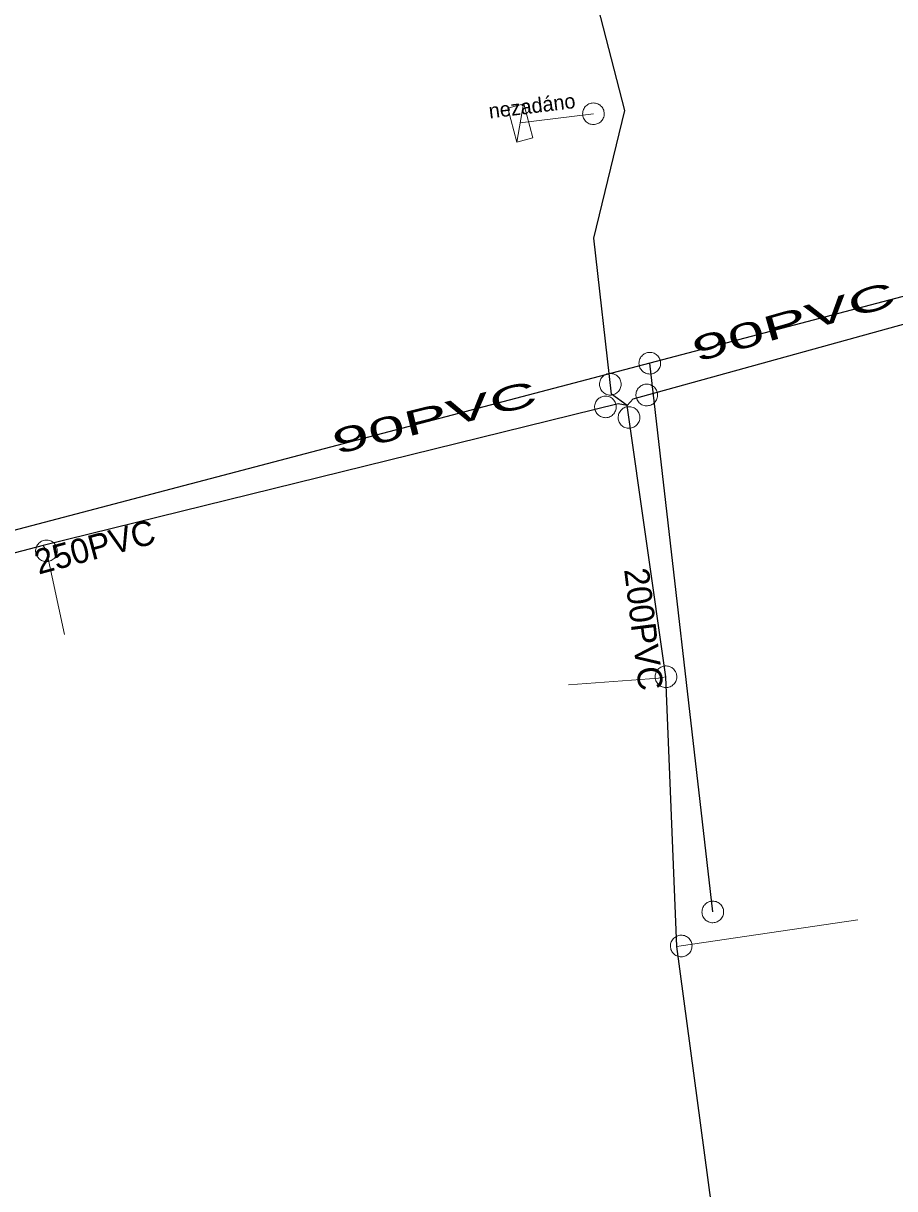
# Model space of a CAD drawing. Extents: x -741806 to -738704, y -1059275 to -1055387.
# Drawn here: x -740624.24 to -740588.96, y -1057303.21 to -1057256.02 of the extents above; entities that cross this region are included whole.
import ezdxf

# ---------------------------------------------------------------- set-up
doc = ezdxf.new("R2010")
doc.units = 0
doc.header["$LTSCALE"] = 0.4
for name, color, linetype, lineweight in [('2', 7, 'Continuous', 25), ('21', 7, 'Continuous', 13), ('3', 7, 'Continuous', 13), ('46', 7, 'Continuous', 13), ('51', 7, 'Continuous', 13), ('52', 7, 'Continuous', 25), ('56', 7, 'Continuous', 13)]:
    doc.layers.add(name, color=color, linetype=linetype, lineweight=lineweight)
for name, color, linetype in [('5', 7, 'Continuous'), ('53', 7, 'Continuous'), ('55', 7, 'Continuous')]:
    doc.layers.add(name, color=color, linetype=linetype)

msp = doc.modelspace()

# ---------------------------------------------------------------- linework, layer by layer
at = {"layer": '2'}
for p in [(-740573.78, -1057263.169), (-740596.329, -1057292)]:
    msp.add_line(p, (-740598.879, -1057269.78), dxfattribs=at)
msp.add_lwpolyline([(-740598.879, -1057269.78), (-740643.57, -1057281.54), (-740672.23, -1057290.27), (-740701.8, -1057300.899)], dxfattribs=at)
at = {"layer": '21'}
for points in [[(-740623.436, -1057277.166), (-740623.3, -1057277.379), (-740622.572, -1057280.771)], [(-740598.223, -1057282.477), (-740598.526, -1057282.531), (-740602.17, -1057282.806)], [(-740597.782, -1057293.399), (-740597.605, -1057293.378), (-740590.458, -1057292.324)]]:
    msp.add_lwpolyline(points, dxfattribs=at)
at = {"layer": '3'}
for points in [[(-740601.254, -1057259.251), (-740601.297, -1057259.264), (-740601.34, -1057259.28), (-740601.381, -1057259.302), (-740601.419, -1057259.326), (-740601.454, -1057259.356), (-740601.487, -1057259.389), (-740601.515, -1057259.424), (-740601.54, -1057259.463), (-740601.559, -1057259.504), (-740601.576, -1057259.547), (-740601.587, -1057259.591), (-740601.594, -1057259.637), (-740601.596, -1057259.682), (-740601.594, -1057259.728), (-740601.586, -1057259.773), (-740601.574, -1057259.818), (-740601.556, -1057259.86), (-740601.536, -1057259.9), (-740601.51, -1057259.939), (-740601.481, -1057259.974), (-740601.448, -1057260.006), (-740601.413, -1057260.034), (-740601.374, -1057260.059), (-740601.333, -1057260.08), (-740601.29, -1057260.096), (-740601.245, -1057260.106), (-740601.201, -1057260.114), (-740601.154, -1057260.116), (-740601.109, -1057260.113), (-740601.063, -1057260.105), (-740601.02, -1057260.093), (-740600.977, -1057260.076), (-740600.936, -1057260.055), (-740600.898, -1057260.029), (-740600.863, -1057260.001), (-740600.83, -1057259.968), (-740600.803, -1057259.932), (-740600.777, -1057259.893), (-740600.758, -1057259.853), (-740600.742, -1057259.81), (-740600.73, -1057259.765), (-740600.723, -1057259.72), (-740600.72, -1057259.674), (-740600.723, -1057259.629), (-740600.731, -1057259.583), (-740600.743, -1057259.539), (-740600.76, -1057259.497), (-740600.781, -1057259.456), (-740600.807, -1057259.418), (-740600.837, -1057259.382), (-740600.869, -1057259.351), (-740600.904, -1057259.322), (-740600.943, -1057259.298), (-740600.984, -1057259.277), (-740601.027, -1057259.261), (-740601.072, -1057259.249), (-740601.116, -1057259.243), (-740601.163, -1057259.241), (-740601.208, -1057259.244), (-740601.253, -1057259.251)], [(-740598.928, -1057269.344), (-740598.972, -1057269.352), (-740599.016, -1057269.364), (-740599.06, -1057269.382), (-740599.099, -1057269.402), (-740599.138, -1057269.428), (-740599.174, -1057269.457), (-740599.205, -1057269.49), (-740599.234, -1057269.525), (-740599.258, -1057269.564), (-740599.279, -1057269.605), (-740599.295, -1057269.648), (-740599.307, -1057269.693), (-740599.313, -1057269.738), (-740599.315, -1057269.783), (-740599.312, -1057269.829), (-740599.305, -1057269.875), (-740599.292, -1057269.919), (-740599.276, -1057269.961), (-740599.254, -1057270.002), (-740599.229, -1057270.04), (-740599.199, -1057270.075), (-740599.168, -1057270.107), (-740599.131, -1057270.136), (-740599.093, -1057270.16), (-740599.051, -1057270.181), (-740599.008, -1057270.196), (-740598.965, -1057270.208), (-740598.919, -1057270.215), (-740598.873, -1057270.217), (-740598.827, -1057270.213), (-740598.783, -1057270.206), (-740598.739, -1057270.194), (-740598.695, -1057270.177), (-740598.655, -1057270.155), (-740598.617, -1057270.131), (-740598.581, -1057270.102), (-740598.55, -1057270.069), (-740598.521, -1057270.032), (-740598.497, -1057269.994), (-740598.477, -1057269.954), (-740598.46, -1057269.911), (-740598.448, -1057269.866), (-740598.441, -1057269.821), (-740598.44, -1057269.775), (-740598.443, -1057269.73), (-740598.45, -1057269.684), (-740598.462, -1057269.64), (-740598.479, -1057269.598), (-740598.501, -1057269.557), (-740598.526, -1057269.519), (-740598.556, -1057269.484), (-740598.588, -1057269.451), (-740598.624, -1057269.423), (-740598.662, -1057269.398), (-740598.704, -1057269.378), (-740598.747, -1057269.362), (-740598.79, -1057269.351), (-740598.836, -1057269.344), (-740598.882, -1057269.342), (-740598.927, -1057269.344)], [(-740596.378, -1057291.564), (-740596.422, -1057291.572), (-740596.466, -1057291.584), (-740596.51, -1057291.602), (-740596.549, -1057291.622), (-740596.588, -1057291.648), (-740596.624, -1057291.677), (-740596.655, -1057291.71), (-740596.684, -1057291.745), (-740596.708, -1057291.784), (-740596.729, -1057291.825), (-740596.745, -1057291.868), (-740596.757, -1057291.913), (-740596.763, -1057291.958), (-740596.765, -1057292.003), (-740596.762, -1057292.049), (-740596.755, -1057292.095), (-740596.742, -1057292.139), (-740596.726, -1057292.181), (-740596.704, -1057292.222), (-740596.679, -1057292.26), (-740596.649, -1057292.295), (-740596.618, -1057292.327), (-740596.581, -1057292.356), (-740596.543, -1057292.38), (-740596.501, -1057292.401), (-740596.458, -1057292.416), (-740596.415, -1057292.428), (-740596.369, -1057292.435), (-740596.323, -1057292.437), (-740596.277, -1057292.433), (-740596.233, -1057292.426), (-740596.189, -1057292.414), (-740596.145, -1057292.397), (-740596.105, -1057292.375), (-740596.067, -1057292.351), (-740596.031, -1057292.322), (-740596, -1057292.289), (-740595.971, -1057292.252), (-740595.947, -1057292.214), (-740595.927, -1057292.174), (-740595.91, -1057292.131), (-740595.898, -1057292.086), (-740595.891, -1057292.041), (-740595.89, -1057291.995), (-740595.893, -1057291.95), (-740595.9, -1057291.904), (-740595.912, -1057291.86), (-740595.929, -1057291.818), (-740595.951, -1057291.777), (-740595.976, -1057291.739), (-740596.006, -1057291.704), (-740596.038, -1057291.671), (-740596.074, -1057291.643), (-740596.112, -1057291.618), (-740596.154, -1057291.598), (-740596.197, -1057291.582), (-740596.24, -1057291.571), (-740596.286, -1057291.564), (-740596.332, -1057291.562), (-740596.377, -1057291.564)]]:
    msp.add_lwpolyline(points, dxfattribs=at)
at = {"layer": '46'}
msp.add_line((-740603.983, -1057259.277), (-740604.257, -1057260.822), dxfattribs=at)
msp.add_lwpolyline([(-740603.981, -1057259.277), (-740603.614, -1057260.649), (-740604.259, -1057260.822), (-740604.626, -1057259.45)], close=True, dxfattribs=at)
at = {"layer": '51'}
for points in [[(-740600.038, -1057270.632), (-740600.039, -1057270.587), (-740600.047, -1057270.542), (-740600.059, -1057270.497), (-740600.075, -1057270.455), (-740600.096, -1057270.414), (-740600.12, -1057270.375), (-740600.15, -1057270.34), (-740600.182, -1057270.307), (-740600.218, -1057270.279), (-740600.255, -1057270.254), (-740600.297, -1057270.233), (-740600.34, -1057270.216), (-740600.384, -1057270.204), (-740600.429, -1057270.197), (-740600.475, -1057270.195), (-740600.521, -1057270.197), (-740600.566, -1057270.204), (-740600.61, -1057270.216), (-740600.652, -1057270.233), (-740600.694, -1057270.254), (-740600.732, -1057270.279), (-740600.767, -1057270.307), (-740600.799, -1057270.34), (-740600.829, -1057270.375), (-740600.853, -1057270.414), (-740600.875, -1057270.455), (-740600.891, -1057270.497), (-740600.902, -1057270.542), (-740600.91, -1057270.587), (-740600.913, -1057270.633), (-740600.91, -1057270.678), (-740600.902, -1057270.723), (-740600.891, -1057270.768), (-740600.875, -1057270.81), (-740600.853, -1057270.851), (-740600.829, -1057270.89), (-740600.799, -1057270.925), (-740600.767, -1057270.958), (-740600.732, -1057270.986), (-740600.694, -1057271.011), (-740600.652, -1057271.032), (-740600.61, -1057271.049), (-740600.566, -1057271.06), (-740600.521, -1057271.068), (-740600.475, -1057271.07), (-740600.429, -1057271.068), (-740600.384, -1057271.06), (-740600.34, -1057271.049), (-740600.297, -1057271.032), (-740600.255, -1057271.011), (-740600.218, -1057270.986), (-740600.182, -1057270.958), (-740600.15, -1057270.925), (-740600.12, -1057270.89), (-740600.096, -1057270.851), (-740600.075, -1057270.81), (-740600.059, -1057270.768), (-740600.047, -1057270.723), (-740600.039, -1057270.678), (-740600.038, -1057270.633)], [(-740598.579, -1057270.951), (-740598.593, -1057270.908), (-740598.612, -1057270.866), (-740598.635, -1057270.826), (-740598.662, -1057270.79), (-740598.693, -1057270.756), (-740598.728, -1057270.725), (-740598.765, -1057270.699), (-740598.805, -1057270.676), (-740598.847, -1057270.658), (-740598.89, -1057270.644), (-740598.935, -1057270.635), (-740598.981, -1057270.63), (-740599.027, -1057270.63), (-740599.072, -1057270.635), (-740599.117, -1057270.646), (-740599.161, -1057270.66), (-740599.202, -1057270.679), (-740599.241, -1057270.702), (-740599.278, -1057270.73), (-740599.312, -1057270.761), (-740599.342, -1057270.795), (-740599.369, -1057270.832), (-740599.391, -1057270.872), (-740599.41, -1057270.914), (-740599.424, -1057270.958), (-740599.433, -1057271.003), (-740599.437, -1057271.048), (-740599.437, -1057271.094), (-740599.432, -1057271.14), (-740599.422, -1057271.185), (-740599.407, -1057271.227), (-740599.389, -1057271.269), (-740599.365, -1057271.309), (-740599.338, -1057271.345), (-740599.307, -1057271.379), (-740599.273, -1057271.41), (-740599.236, -1057271.436), (-740599.196, -1057271.459), (-740599.154, -1057271.477), (-740599.11, -1057271.491), (-740599.065, -1057271.5), (-740599.019, -1057271.505), (-740598.974, -1057271.504), (-740598.929, -1057271.499), (-740598.884, -1057271.489), (-740598.84, -1057271.475), (-740598.799, -1057271.455), (-740598.759, -1057271.433), (-740598.722, -1057271.405), (-740598.688, -1057271.374), (-740598.658, -1057271.34), (-740598.631, -1057271.303), (-740598.609, -1057271.263), (-740598.59, -1057271.221), (-740598.577, -1057271.177), (-740598.567, -1057271.132), (-740598.563, -1057271.087), (-740598.564, -1057271.041), (-740598.569, -1057270.995), (-740598.579, -1057270.952)], [(-740601.097, -1057271.653), (-740601.084, -1057271.696), (-740601.067, -1057271.738), (-740601.044, -1057271.779), (-740601.019, -1057271.816), (-740600.988, -1057271.85), (-740600.955, -1057271.882), (-740600.918, -1057271.909), (-740600.879, -1057271.934), (-740600.838, -1057271.952), (-740600.795, -1057271.967), (-740600.75, -1057271.978), (-740600.704, -1057271.984), (-740600.658, -1057271.985), (-740600.613, -1057271.981), (-740600.568, -1057271.972), (-740600.524, -1057271.959), (-740600.482, -1057271.942), (-740600.442, -1057271.92), (-740600.404, -1057271.893), (-740600.369, -1057271.863), (-740600.339, -1057271.829), (-740600.31, -1057271.793), (-740600.287, -1057271.754), (-740600.267, -1057271.713), (-740600.252, -1057271.669), (-740600.242, -1057271.624), (-740600.236, -1057271.579), (-740600.236, -1057271.533), (-740600.24, -1057271.487), (-740600.248, -1057271.442), (-740600.261, -1057271.399), (-740600.279, -1057271.357), (-740600.301, -1057271.316), (-740600.327, -1057271.279), (-740600.357, -1057271.245), (-740600.391, -1057271.213), (-740600.427, -1057271.186), (-740600.466, -1057271.161), (-740600.508, -1057271.143), (-740600.551, -1057271.128), (-740600.596, -1057271.117), (-740600.641, -1057271.111), (-740600.687, -1057271.111), (-740600.732, -1057271.114), (-740600.778, -1057271.123), (-740600.822, -1057271.136), (-740600.864, -1057271.154), (-740600.904, -1057271.176), (-740600.941, -1057271.202), (-740600.976, -1057271.233), (-740601.007, -1057271.266), (-740601.035, -1057271.302), (-740601.058, -1057271.341), (-740601.078, -1057271.382), (-740601.093, -1057271.426), (-740601.104, -1057271.471), (-740601.109, -1057271.516), (-740601.11, -1057271.562), (-740601.106, -1057271.608), (-740601.097, -1057271.652)], [(-740599.781, -1057271.545), (-740599.825, -1057271.553), (-740599.868, -1057271.566), (-740599.911, -1057271.585), (-740599.951, -1057271.606), (-740599.988, -1057271.633), (-740600.023, -1057271.663), (-740600.054, -1057271.697), (-740600.082, -1057271.733), (-740600.105, -1057271.773), (-740600.124, -1057271.814), (-740600.139, -1057271.858), (-740600.15, -1057271.902), (-740600.156, -1057271.948), (-740600.156, -1057271.993), (-740600.152, -1057272.039), (-740600.143, -1057272.084), (-740600.13, -1057272.128), (-740600.112, -1057272.17), (-740600.089, -1057272.21), (-740600.062, -1057272.248), (-740600.032, -1057272.282), (-740599.999, -1057272.313), (-740599.962, -1057272.34), (-740599.923, -1057272.364), (-740599.881, -1057272.383), (-740599.838, -1057272.398), (-740599.794, -1057272.408), (-740599.748, -1057272.414), (-740599.702, -1057272.414), (-740599.656, -1057272.411), (-740599.612, -1057272.402), (-740599.569, -1057272.388), (-740599.526, -1057272.37), (-740599.486, -1057272.348), (-740599.449, -1057272.322), (-740599.414, -1057272.291), (-740599.383, -1057272.258), (-740599.355, -1057272.222), (-740599.332, -1057272.182), (-740599.313, -1057272.141), (-740599.298, -1057272.097), (-740599.287, -1057272.052), (-740599.282, -1057272.007), (-740599.281, -1057271.961), (-740599.285, -1057271.916), (-740599.294, -1057271.87), (-740599.308, -1057271.827), (-740599.325, -1057271.785), (-740599.348, -1057271.745), (-740599.375, -1057271.707), (-740599.405, -1057271.673), (-740599.438, -1057271.641), (-740599.475, -1057271.614), (-740599.514, -1057271.591), (-740599.556, -1057271.571), (-740599.599, -1057271.556), (-740599.643, -1057271.546), (-740599.689, -1057271.541), (-740599.735, -1057271.54), (-740599.78, -1057271.545)], [(-740623.064, -1057277.746), (-740623.027, -1057277.72), (-740622.993, -1057277.69), (-740622.961, -1057277.656), (-740622.935, -1057277.619), (-740622.912, -1057277.58), (-740622.892, -1057277.537), (-740622.879, -1057277.494), (-740622.868, -1057277.449), (-740622.864, -1057277.404), (-740622.864, -1057277.358), (-740622.868, -1057277.313), (-740622.877, -1057277.267), (-740622.891, -1057277.224), (-740622.909, -1057277.182), (-740622.932, -1057277.142), (-740622.959, -1057277.105), (-740622.989, -1057277.071), (-740623.023, -1057277.04), (-740623.061, -1057277.013), (-740623.1, -1057276.99), (-740623.142, -1057276.972), (-740623.185, -1057276.957), (-740623.23, -1057276.947), (-740623.275, -1057276.942), (-740623.322, -1057276.942), (-740623.367, -1057276.947), (-740623.411, -1057276.956), (-740623.456, -1057276.97), (-740623.497, -1057276.989), (-740623.538, -1057277.011), (-740623.574, -1057277.038), (-740623.608, -1057277.068), (-740623.639, -1057277.102), (-740623.666, -1057277.139), (-740623.689, -1057277.178), (-740623.708, -1057277.221), (-740623.722, -1057277.264), (-740623.733, -1057277.309), (-740623.737, -1057277.354), (-740623.737, -1057277.4), (-740623.733, -1057277.445), (-740623.724, -1057277.491), (-740623.709, -1057277.534), (-740623.692, -1057277.576), (-740623.668, -1057277.616), (-740623.642, -1057277.653), (-740623.611, -1057277.687), (-740623.578, -1057277.718), (-740623.54, -1057277.745), (-740623.5, -1057277.768), (-740623.459, -1057277.786), (-740623.416, -1057277.802), (-740623.371, -1057277.811), (-740623.325, -1057277.816), (-740623.279, -1057277.816), (-740623.233, -1057277.811), (-740623.189, -1057277.802), (-740623.145, -1057277.788), (-740623.103, -1057277.77), (-740623.064, -1057277.747)], [(-740598.653, -1057282.553), (-740598.643, -1057282.597), (-740598.628, -1057282.64), (-740598.608, -1057282.682), (-740598.585, -1057282.72), (-740598.557, -1057282.757), (-740598.526, -1057282.791), (-740598.491, -1057282.821), (-740598.454, -1057282.847), (-740598.414, -1057282.869), (-740598.372, -1057282.887), (-740598.328, -1057282.9), (-740598.283, -1057282.909), (-740598.237, -1057282.913), (-740598.192, -1057282.912), (-740598.146, -1057282.906), (-740598.101, -1057282.896), (-740598.058, -1057282.881), (-740598.017, -1057282.862), (-740597.977, -1057282.838), (-740597.941, -1057282.81), (-740597.908, -1057282.778), (-740597.877, -1057282.745), (-740597.851, -1057282.706), (-740597.829, -1057282.667), (-740597.811, -1057282.624), (-740597.798, -1057282.58), (-740597.789, -1057282.536), (-740597.785, -1057282.49), (-740597.786, -1057282.444), (-740597.792, -1057282.398), (-740597.802, -1057282.354), (-740597.817, -1057282.311), (-740597.837, -1057282.269), (-740597.86, -1057282.231), (-740597.888, -1057282.194), (-740597.919, -1057282.16), (-740597.954, -1057282.131), (-740597.991, -1057282.104), (-740598.032, -1057282.082), (-740598.073, -1057282.064), (-740598.118, -1057282.051), (-740598.163, -1057282.042), (-740598.208, -1057282.039), (-740598.254, -1057282.039), (-740598.299, -1057282.045), (-740598.344, -1057282.055), (-740598.387, -1057282.071), (-740598.429, -1057282.089), (-740598.468, -1057282.113), (-740598.505, -1057282.141), (-740598.538, -1057282.173), (-740598.568, -1057282.206), (-740598.594, -1057282.245), (-740598.616, -1057282.284), (-740598.634, -1057282.327), (-740598.648, -1057282.371), (-740598.656, -1057282.415), (-740598.66, -1057282.462), (-740598.659, -1057282.507), (-740598.653, -1057282.552)], [(-740597.171, -1057293.326), (-740597.178, -1057293.282), (-740597.19, -1057293.238), (-740597.207, -1057293.195), (-740597.228, -1057293.155), (-740597.254, -1057293.117), (-740597.283, -1057293.081), (-740597.316, -1057293.05), (-740597.352, -1057293.021), (-740597.391, -1057292.997), (-740597.432, -1057292.977), (-740597.475, -1057292.961), (-740597.52, -1057292.949), (-740597.565, -1057292.942), (-740597.61, -1057292.941), (-740597.656, -1057292.944), (-740597.702, -1057292.952), (-740597.746, -1057292.964), (-740597.788, -1057292.981), (-740597.828, -1057293.003), (-740597.867, -1057293.029), (-740597.901, -1057293.058), (-740597.934, -1057293.09), (-740597.962, -1057293.127), (-740597.986, -1057293.165), (-740598.007, -1057293.206), (-740598.023, -1057293.25), (-740598.034, -1057293.293), (-740598.04, -1057293.339), (-740598.042, -1057293.385), (-740598.039, -1057293.431), (-740598.031, -1057293.475), (-740598.019, -1057293.519), (-740598.001, -1057293.562), (-740597.981, -1057293.602), (-740597.955, -1057293.64), (-740597.925, -1057293.676), (-740597.892, -1057293.707), (-740597.857, -1057293.736), (-740597.818, -1057293.76), (-740597.777, -1057293.78), (-740597.734, -1057293.796), (-740597.689, -1057293.808), (-740597.644, -1057293.814), (-740597.598, -1057293.816), (-740597.553, -1057293.813), (-740597.507, -1057293.805), (-740597.463, -1057293.792), (-740597.421, -1057293.776), (-740597.38, -1057293.754), (-740597.342, -1057293.728), (-740597.307, -1057293.699), (-740597.275, -1057293.667), (-740597.247, -1057293.63), (-740597.222, -1057293.592), (-740597.202, -1057293.551), (-740597.186, -1057293.507), (-740597.175, -1057293.464), (-740597.169, -1057293.418), (-740597.167, -1057293.372), (-740597.17, -1057293.327)]]:
    msp.add_lwpolyline(points, dxfattribs=at)
at = {"layer": '52'}
for points in [[(-740599.789, -1057271.49), (-740600.43, -1057271.03), (-740601.149, -1057264.71), (-740599.89, -1057259.55), (-740605.469, -1057237.879), (-740606.21, -1057235.75), (-740610.079, -1057216.44), (-740610.699, -1057213.46), (-740613.21, -1057198.96), (-740635.57, -1057204.919), (-740654.67, -1057209.71), (-740658.96, -1057210.78), (-740671.342, -1057213.918), (-740678.14, -1057215.639), (-740680.199, -1057216.11)], [(-740599.789, -1057271.49), (-740599.544, -1057271.217), (-740577.079, -1057265.007), (-740575.563, -1057264.566), (-740574.636, -1057264.455), (-740573.886, -1057264.318), (-740573.23, -1057264.149)], [(-740599.789, -1057271.49), (-740600.159, -1057271.422), (-740623.436, -1057277.166), (-740641.474, -1057281.881), (-740643.675, -1057282.756), (-740644.41, -1057282.96)], [(-740592.169, -1057336.51), (-740592.884, -1057329.919), (-740597.782, -1057293.399), (-740598.223, -1057282.477), (-740599.789, -1057271.49)]]:
    msp.add_lwpolyline(points, dxfattribs=at)
at = {"layer": '56'}
msp.add_line((-740604.12, -1057260.05), (-740601.16, -1057259.679), dxfattribs=at)

# ---------------------------------------------------------------- texts
at = {"layer": '5'}
for s, rotation, p in [('250PVC', 15, (-740623.62, -1057278.342)), ('200PVC', 277, (-740599.918, -1057278.135))]:
    msp.add_text(s, height=1, rotation=rotation, dxfattribs=at).set_placement(p)
at = {"layer": '53', "width": 2}
for rotation, p in [(16, (-740596.991, -1057269.745)), (14, (-740611.583, -1057273.483))]:
    msp.add_text('90PVC ', height=1, rotation=rotation, dxfattribs=at).set_placement(p)
at = {"layer": '55'}
msp.add_text('nezadáno  ', height=0.6, rotation=7, dxfattribs=at).set_placement((-740605.359, -1057259.871))

doc.saveas('drawing.dxf')
